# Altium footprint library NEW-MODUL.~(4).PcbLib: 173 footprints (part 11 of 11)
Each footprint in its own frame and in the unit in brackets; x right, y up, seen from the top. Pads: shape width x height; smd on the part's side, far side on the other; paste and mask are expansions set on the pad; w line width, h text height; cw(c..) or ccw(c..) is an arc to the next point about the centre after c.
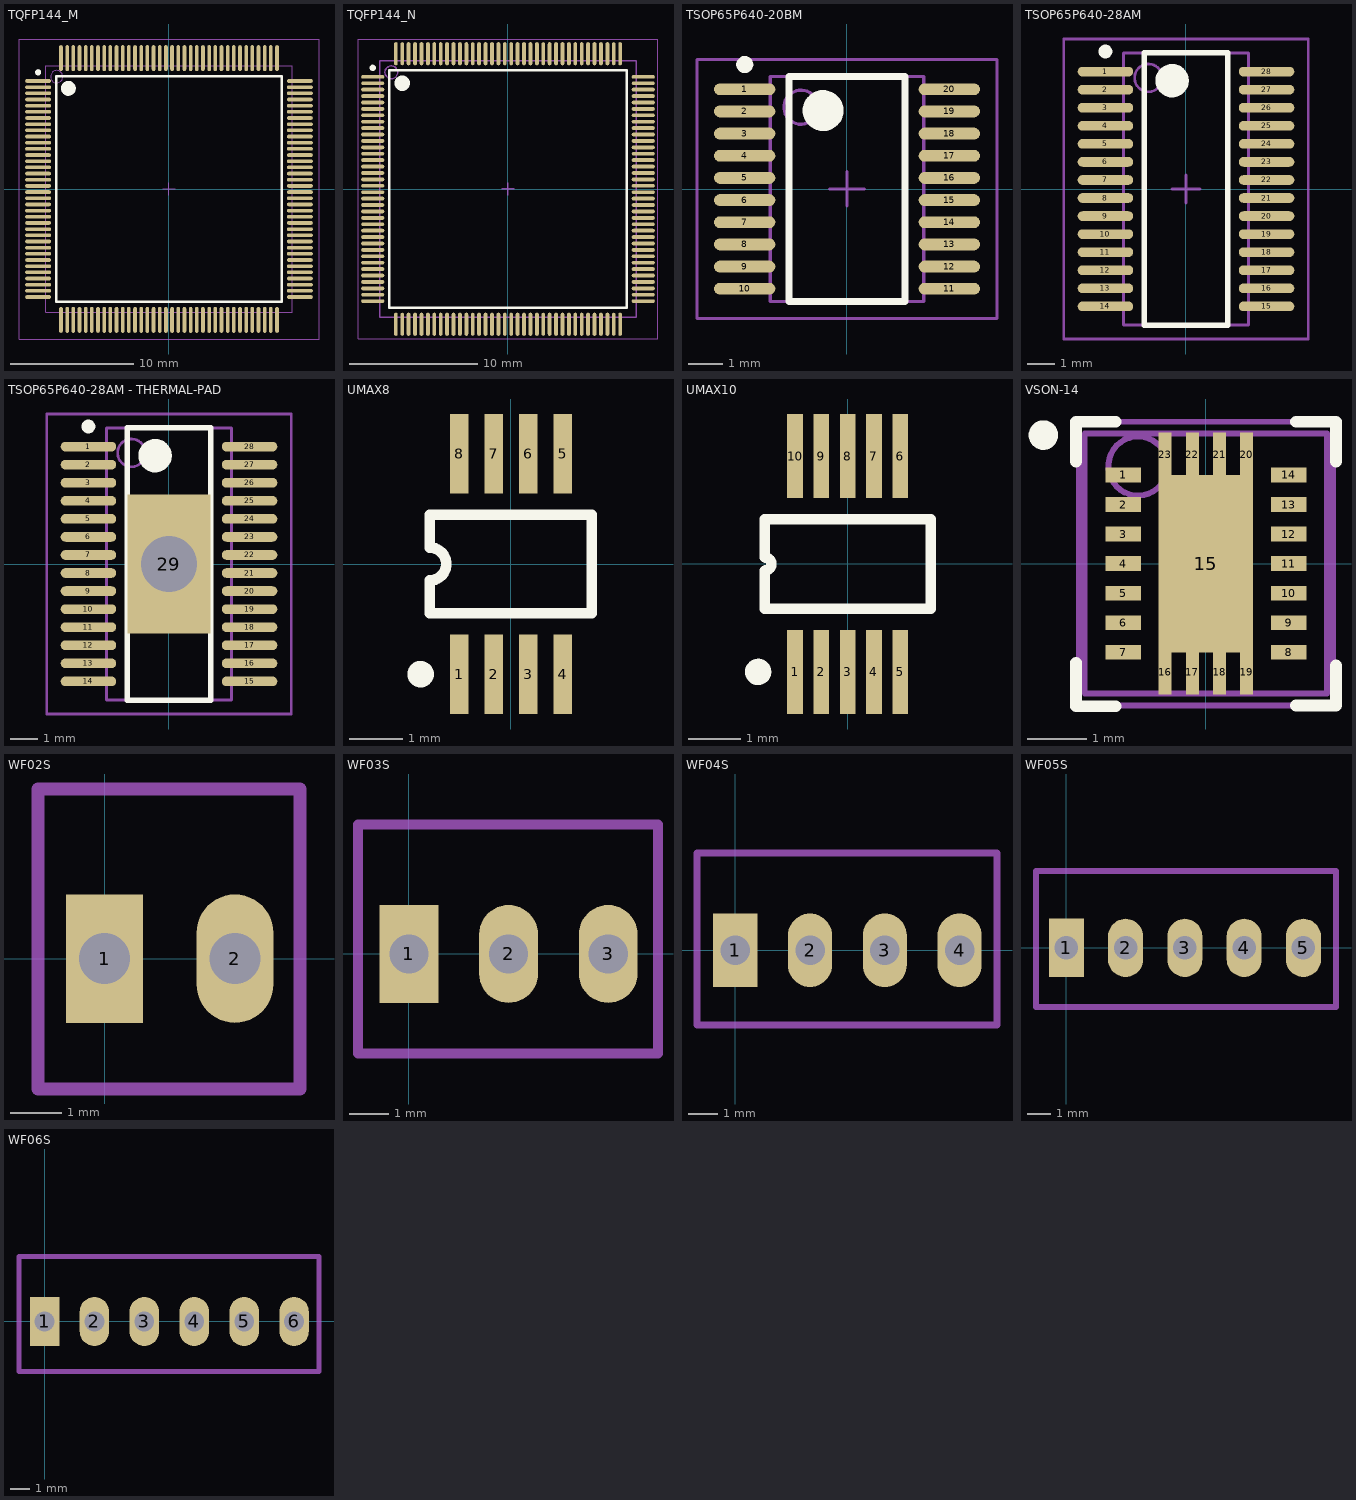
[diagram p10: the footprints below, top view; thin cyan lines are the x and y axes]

## TQFP144_M [mm] "Thin QFP, 144-Leads, Body 20x20mm, Pitch 0.5mm, IPC Low Density"
height 1.6
pads (144):
  oval 2.1x0.3 smd: 1(-10.6,8.75) 2(-10.6,8.25) 3(-10.6,7.75) 4(-10.6,7.25) 5(-10.6,6.75) 6(-10.6,6.25) 7(-10.6,5.75) 8(-10.6,5.25) 9(-10.6,4.75) 10(-10.6,4.25) 11(-10.6,3.75) 12(-10.6,3.25) 13(-10.6,2.75) 14(-10.6,2.25) 15(-10.6,1.75) 16(-10.6,1.25) 17(-10.6,0.75) 18(-10.6,0.25) 19(-10.6,-0.25) 20(-10.6,-0.75) 21(-10.6,-1.25) 22(-10.6,-1.75) 23(-10.6,-2.25) 24(-10.6,-2.75) 25(-10.6,-3.25) 26(-10.6,-3.75) 27(-10.6,-4.25) 28(-10.6,-4.75) 29(-10.6,-5.25) 30(-10.6,-5.75) 31(-10.6,-6.25) 32(-10.6,-6.75) 33(-10.6,-7.25) 34(-10.6,-7.75) 35(-10.6,-8.25) 36(-10.6,-8.75) 73(10.6,-8.75) 74(10.6,-8.25) 75(10.6,-7.75) 76(10.6,-7.25) 77(10.6,-6.75) 78(10.6,-6.25) 79(10.6,-5.75) 80(10.6,-5.25) 81(10.6,-4.75) 82(10.6,-4.25) 83(10.6,-3.75) 84(10.6,-3.25) 85(10.6,-2.75) 86(10.6,-2.25) 87(10.6,-1.75) 88(10.6,-1.25) 89(10.6,-0.75) 90(10.6,-0.25) 91(10.6,0.25) 92(10.6,0.75) 93(10.6,1.25) 94(10.6,1.75) 95(10.6,2.25) 96(10.6,2.75) 97(10.6,3.25) 98(10.6,3.75) 99(10.6,4.25) 100(10.6,4.75) 101(10.6,5.25) 102(10.6,5.75) 103(10.6,6.25) 104(10.6,6.75) 105(10.6,7.25) 106(10.6,7.75) 107(10.6,8.25) 108(10.6,8.75)
  oval 0.3x2.1 smd: 37(-8.75,-10.6) 38(-8.25,-10.6) 39(-7.75,-10.6) 40(-7.25,-10.6) 41(-6.75,-10.6) 42(-6.25,-10.6) 43(-5.75,-10.6) 44(-5.25,-10.6) 45(-4.75,-10.6) 46(-4.25,-10.6) 47(-3.75,-10.6) 48(-3.25,-10.6) 49(-2.75,-10.6) 50(-2.25,-10.6) 51(-1.75,-10.6) 52(-1.25,-10.6) 53(-0.75,-10.6) 54(-0.25,-10.6) 55(0.25,-10.6) 56(0.75,-10.6) 57(1.25,-10.6) 58(1.75,-10.6) 59(2.25,-10.6) 60(2.75,-10.6) 61(3.25,-10.6) 62(3.75,-10.6) 63(4.25,-10.6) 64(4.75,-10.6) 65(5.25,-10.6) 66(5.75,-10.6) 67(6.25,-10.6) 68(6.75,-10.6) 69(7.25,-10.6) 70(7.75,-10.6) 71(8.25,-10.6) 72(8.75,-10.6) 109(8.75,10.6) 110(8.25,10.6) 111(7.75,10.6) 112(7.25,10.6) 113(6.75,10.6) 114(6.25,10.6) 115(5.75,10.6) 116(5.25,10.6) 117(4.75,10.6) 118(4.25,10.6) 119(3.75,10.6) 120(3.25,10.6) 121(2.75,10.6) 122(2.25,10.6) 123(1.75,10.6) 124(1.25,10.6) 125(0.75,10.6) 126(0.25,10.6) 127(-0.25,10.6) 128(-0.75,10.6) 129(-1.25,10.6) 130(-1.75,10.6) 131(-2.25,10.6) 132(-2.75,10.6) 133(-3.25,10.6) 134(-3.75,10.6) 135(-4.25,10.6) 136(-4.75,10.6) 137(-5.25,10.6) 138(-5.75,10.6) 139(-6.25,10.6) 140(-6.75,10.6) 141(-7.25,10.6) 142(-7.75,10.6) 143(-8.25,10.6) 144(-8.75,10.6)
Top Overlay:
  circle w0.6: c-8.15,8.15 r0.3
  circle w0.25: c-10.6,9.45 r0.125
  lines w0.2: -9.15,-9.15 9.15,-9.15 9.15,9.15 -9.15,9.15 -9.15,-9.15
Mechanical 13:
  circle w0.1: c-9.1,9.1 r0.5
  lines w0.1: -10,-10 10,-10 10,10 -10,10 -10,-10
Mechanical 15:
  lines w0.05: -12.15,-12.15 12.15,-12.15 12.15,12.15 -12.15,12.15 -12.15,-12.15
  lines w0.1: -0.5,0 0.5,0 ; 0,-0.5 0,0.5
3D body: height 1.6, standoff 0, extent -10,-10 10,10

## TQFP144_N [mm] "Thin QFP, 144-Leads, Body 20x20mm, Pitch 0.5mm, IPC Medium Density"
height 1.6
pads (144):
  oval 1.8x0.3 smd: 1(-10.55,8.75) 2(-10.55,8.25) 3(-10.55,7.75) 4(-10.55,7.25) 5(-10.55,6.75) 6(-10.55,6.25) 7(-10.55,5.75) 8(-10.55,5.25) 9(-10.55,4.75) 10(-10.55,4.25) 11(-10.55,3.75) 12(-10.55,3.25) 13(-10.55,2.75) 14(-10.55,2.25) 15(-10.55,1.75) 16(-10.55,1.25) 17(-10.55,0.75) 18(-10.55,0.25) 19(-10.55,-0.25) 20(-10.55,-0.75) 21(-10.55,-1.25) 22(-10.55,-1.75) 23(-10.55,-2.25) 24(-10.55,-2.75) 25(-10.55,-3.25) 26(-10.55,-3.75) 27(-10.55,-4.25) 28(-10.55,-4.75) 29(-10.55,-5.25) 30(-10.55,-5.75) 31(-10.55,-6.25) 32(-10.55,-6.75) 33(-10.55,-7.25) 34(-10.55,-7.75) 35(-10.55,-8.25) 36(-10.55,-8.75) 73(10.55,-8.75) 74(10.55,-8.25) 75(10.55,-7.75) 76(10.55,-7.25) 77(10.55,-6.75) 78(10.55,-6.25) 79(10.55,-5.75) 80(10.55,-5.25) 81(10.55,-4.75) 82(10.55,-4.25) 83(10.55,-3.75) 84(10.55,-3.25) 85(10.55,-2.75) 86(10.55,-2.25) 87(10.55,-1.75) 88(10.55,-1.25) 89(10.55,-0.75) 90(10.55,-0.25) 91(10.55,0.25) 92(10.55,0.75) 93(10.55,1.25) 94(10.55,1.75) 95(10.55,2.25) 96(10.55,2.75) 97(10.55,3.25) 98(10.55,3.75) 99(10.55,4.25) 100(10.55,4.75) 101(10.55,5.25) 102(10.55,5.75) 103(10.55,6.25) 104(10.55,6.75) 105(10.55,7.25) 106(10.55,7.75) 107(10.55,8.25) 108(10.55,8.75)
  oval 0.3x1.8 smd: 37(-8.75,-10.55) 38(-8.25,-10.55) 39(-7.75,-10.55) 40(-7.25,-10.55) 41(-6.75,-10.55) 42(-6.25,-10.55) 43(-5.75,-10.55) 44(-5.25,-10.55) 45(-4.75,-10.55) 46(-4.25,-10.55) 47(-3.75,-10.55) 48(-3.25,-10.55) 49(-2.75,-10.55) 50(-2.25,-10.55) 51(-1.75,-10.55) 52(-1.25,-10.55) 53(-0.75,-10.55) 54(-0.25,-10.55) 55(0.25,-10.55) 56(0.75,-10.55) 57(1.25,-10.55) 58(1.75,-10.55) 59(2.25,-10.55) 60(2.75,-10.55) 61(3.25,-10.55) 62(3.75,-10.55) 63(4.25,-10.55) 64(4.75,-10.55) 65(5.25,-10.55) 66(5.75,-10.55) 67(6.25,-10.55) 68(6.75,-10.55) 69(7.25,-10.55) 70(7.75,-10.55) 71(8.25,-10.55) 72(8.75,-10.55) 109(8.75,10.55) 110(8.25,10.55) 111(7.75,10.55) 112(7.25,10.55) 113(6.75,10.55) 114(6.25,10.55) 115(5.75,10.55) 116(5.25,10.55) 117(4.75,10.55) 118(4.25,10.55) 119(3.75,10.55) 120(3.25,10.55) 121(2.75,10.55) 122(2.25,10.55) 123(1.75,10.55) 124(1.25,10.55) 125(0.75,10.55) 126(0.25,10.55) 127(-0.25,10.55) 128(-0.75,10.55) 129(-1.25,10.55) 130(-1.75,10.55) 131(-2.25,10.55) 132(-2.75,10.55) 133(-3.25,10.55) 134(-3.75,10.55) 135(-4.25,10.55) 136(-4.75,10.55) 137(-5.25,10.55) 138(-5.75,10.55) 139(-6.25,10.55) 140(-6.75,10.55) 141(-7.25,10.55) 142(-7.75,10.55) 143(-8.25,10.55) 144(-8.75,10.55)
Top Overlay:
  circle w0.25: c-10.55,9.45 r0.125
  circle w0.6: c-8.25,8.25 r0.3
  lines w0.2: -9.25,-9.25 -9.25,9.25 9.25,9.25 9.25,-9.25 -9.25,-9.25
Mechanical 13:
  circle w0.1: c-9.1,9.1 r0.5
  lines w0.1: -10,-10 -10,10 10,10 10,-10 -10,-10
Mechanical 15:
  lines w0.05: -11.7,-11.7 -11.7,11.7 11.7,11.7 11.7,-11.7 -11.7,-11.7
  lines w0.1: -0.5,0 0.5,0 ; 0,-0.5 0,0.5
3D body: height 1.6, standoff 0, extent -10,-10 10,10

## TSOP65P640-20BM [mm] "TSOP, 20-Leads, Body 6.5x4.4mm, Pitch 0.65mm, IPC Low Density"
height 1.2
pads (20):
  oval 1.8x0.35 smd: 1(-3,2.925) 2(-3,2.275) 3(-3,1.625) 4(-3,0.975) 5(-3,0.325) 6(-3,-0.325) 7(-3,-0.975) 8(-3,-1.625) 9(-3,-2.275) 10(-3,-2.925) 11(3,-2.925) 12(3,-2.275) 13(3,-1.625) 14(3,-0.975) 15(3,-0.325) 16(3,0.325) 17(3,0.975) 18(3,1.625) 19(3,2.275) 20(3,2.925)
Top Overlay:
  circle w0.25: c-3,3.65 r0.125
  circle w0.6: c-0.7,2.3 r0.3
  lines w0.2: -1.7,-3.3 -1.7,3.3 1.7,3.3 1.7,-3.3 -1.7,-3.3
Mechanical 13:
  circle w0.1: c-1.35,2.4 r0.5
  lines w0.1: -2.25,-3.3 -2.25,3.3 2.25,3.3 2.25,-3.3 -2.25,-3.3
Mechanical 15:
  lines w0.1: -0.5,0 0.5,0 ; 0,-0.5 0,0.5 ; -4.4,-3.8 -4.4,3.8 4.4,3.8 4.4,-3.8 -4.4,-3.8
3D body "User Library-TSSOP-20 6_6x4_4.STEP": height 1.12, standoff 0.02, extent -3.2,-3.3 3.2,3.3

## TSOP65P640-28AM [mm] "TSOP, 28-Leads, Body 9.7x4.4mm, Pitch 0.65mm, IPC Low Density"
height 1.1
pads (28):
  oval 2x0.35 smd: 1(-2.9,4.225) 2(-2.9,3.575) 3(-2.9,2.925) 4(-2.9,2.275) 5(-2.9,1.625) 6(-2.9,0.975) 7(-2.9,0.325) 8(-2.9,-0.325) 9(-2.9,-0.975) 10(-2.9,-1.625) 11(-2.9,-2.275) 12(-2.9,-2.925) 13(-2.9,-3.575) 14(-2.9,-4.225) 15(2.9,-4.225) 16(2.9,-3.575) 17(2.9,-2.925) 18(2.9,-2.275) 19(2.9,-1.625) 20(2.9,-0.975) 21(2.9,-0.325) 22(2.9,0.325) 23(2.9,0.975) 24(2.9,1.625) 25(2.9,2.275) 26(2.9,2.925) 27(2.9,3.575) 28(2.9,4.225)
Top Overlay:
  circle w0.25: c-2.9,4.95 r0.125
  circle w0.6: c-0.5,3.9 r0.3
  lines w0.2: -1.5,-4.9 -1.5,4.9 1.5,4.9 1.5,-4.9 -1.5,-4.9
Mechanical 13:
  circle w0.1: c-1.35,4 r0.5
  lines w0.1: -2.25,-4.9 -2.25,4.9 2.25,4.9 2.25,-4.9 -2.25,-4.9
Mechanical 15:
  lines w0.1: -0.5,0 0.5,0 ; 0,-0.5 0,0.5 ; -4.4,-5.4 -4.4,5.4 4.4,5.4 4.4,-5.4 -4.4,-5.4
3D body "SW3dPS-TSSOP-28_P065.STEP": height 1.09, standoff 0.01, extent -3.206,-4.85 3.207,4.85

## TSOP65P640-28AM - THERMAL-PAD [mm] "TSOP, 28-Leads, Body 9.7x4.4mm, Pitch 0.65mm, IPC Low Density"
height 1.1
pads (29):
  oval 2x0.35 smd: 1(-2.9,4.225) 2(-2.9,3.575) 3(-2.9,2.925) 4(-2.9,2.275) 5(-2.9,1.625) 6(-2.9,0.975) 7(-2.9,0.325) 8(-2.9,-0.325) 9(-2.9,-0.975) 10(-2.9,-1.625) 11(-2.9,-2.275) 12(-2.9,-2.925) 13(-2.9,-3.575) 14(-2.9,-4.225) 15(2.9,-4.225) 16(2.9,-3.575) 17(2.9,-2.925) 18(2.9,-2.275) 19(2.9,-1.625) 20(2.9,-0.975) 21(2.9,-0.325) 22(2.9,0.325) 23(2.9,0.975) 24(2.9,1.625) 25(2.9,2.275) 26(2.9,2.925) 27(2.9,3.575) 28(2.9,4.225)
  rect 3x5 / inner round 2 / far side rect 3x3 hole 2: 29(0,0)
Top Overlay:
  circle w0.25: c-2.9,4.95 r0.125
  circle w0.6: c-0.5,3.9 r0.3
  lines w0.2: -1.5,-4.9 -1.5,4.9 1.5,4.9 1.5,-4.9 -1.5,-4.9
Mechanical 13:
  circle w0.1: c-1.35,4 r0.5
  lines w0.1: -2.25,-4.9 -2.25,4.9 2.25,4.9 2.25,-4.9 -2.25,-4.9
Mechanical 15:
  lines w0.1: -0.5,0 0.5,0 ; 0,-0.5 0,0.5 ; -4.4,-5.4 -4.4,5.4 4.4,5.4 4.4,-5.4 -4.4,-5.4
3D body "SW3dPS-TSSOP-28_P065.STEP": height 1.09, standoff 0.01, extent -3.206,-4.85 3.207,4.85

## UMAX8 [mm] "Shrink Small Outline; 8 Leads; Body Width 3 mm; Pitch 0.65 mm"
height 1.1
pads (8):
  rect 0.35x1.5 smd: 1(-0.975,-2.075) 2(-0.325,-2.075) 3(0.325,-2.075) 4(0.975,-2.075) 5(0.975,2.075) 6(0.325,2.075) 7(-0.325,2.075) 8(-0.975,2.075)
Top Overlay:
  circle w0.25: c-1.7,-2.075 r0.125
  lines w0.2: -1.525,-0.925 -1.525,-0.308 ccw(c-1.525,0) -1.525,0.308 -1.525,0.925 1.525,0.925 1.525,-0.925 -1.525,-0.925
3D body "SW3dPS-uMAX8.STEP": height 0.95, standoff 0, extent -1.5,-2.5 1.5,2.5

## UMAX10 [mm] "Shrink Small Outline; 10 Leads; Body Width 3 mm; Pitch 0.5 mm"
height 1.1
pads (10):
  rect 0.3x1.6 smd: 1(-1,-2.05) 2(-0.5,-2.05) 3(0,-2.05) 4(0.5,-2.05) 5(1,-2.05) 6(1,2.05) 7(0.5,2.05) 8(0,2.05) 9(-0.5,2.05) 10(-1,2.05)
Top Overlay:
  circle w0.25: c-1.7,-2.05 r0.125
  lines w0.2: -1.575,-0.85 -1.575,-0.125 ccw(c-1.575,0) -1.575,0.125 -1.575,0.85 1.575,0.85 1.575,-0.85 -1.575,-0.85
3D body "SW3dPS-uMAX10.STEP": height 0.95, standoff 0, extent -1.5,-2.5 1.5,2.5

## VSON-14 [mm] "PQFN, 24-Leads, Body 5x4mm, Pitch 0.5mm, NSC Recommended"
height 0.8
pads (23):
  rect 0.6x0.25 smd paste-0.2 mask+0.051: 1(-1.4,1.5) 2(-1.4,1) 3(-1.4,0.5) 4(-1.4,0) 5(-1.4,-0.5) 6(-1.4,-1) 7(-1.4,-1.5) 8(1.4,-1.5) 9(1.4,-1) 10(1.4,-0.5) 11(1.4,0) 12(1.4,0.5) 13(1.4,1) 14(1.4,1.5)
  rect 1.6x3 smd paste-1.2 mask+0.051: 15(0,0)
  rect 0.22x0.75 smd paste-0.2 mask+0.051: 16(-0.69,-1.84) 17(-0.23,-1.84) 18(0.23,-1.84) 19(0.69,-1.84) 20(0.69,1.84) 21(0.23,1.84) 22(-0.23,1.84) 23(-0.69,1.84)
Top Overlay:
  circle w0.25: c-2.75,2.175 r0.125
  lines w0.2: -2.2,-1.676 -2.2,-2.413 -1.525,-2.413 ; -2.2,1.725 -2.2,2.4 -1.525,2.4 ; 1.525,-2.4 2.2,-2.4 2.2,-1.725 ; 1.525,2.4 2.2,2.4 2.2,1.725
Mechanical 13:
  circle w0.1: c-1.15,1.65 r0.5
  lines w0.1: -2.05,-2.2 -2.05,2.2 2.05,2.2 2.05,-2.2 -2.05,-2.2
Mechanical 15:
  lines w0.1: -0.5,0 0.5,0 ; 0,-0.5 0,0.5 ; -2.15,-2.4 -2.15,2.4 2.15,2.4 2.15,-2.4 -2.15,-2.4
3D body "User Library-VSON-14-1.step": height 1, standoff -0.05, extent -1.607,-2.101 1.603,2.109

## WF02S [mm]
pads (2):
  rect 1.5x2.5 hole 1: 1(0,0)
  oval 1.5x2.5 hole 1: 2(2.54,0)
Mechanical 15:
  lines w0.254: -1.3,-2.54 3.81,-2.54 3.81,3.302 -1.3,3.302 -1.3,-2.54
3D body "User Library-CI31_2.step": height 11.51, standoff -3.29, extent -1.27,-2.521 3.81,3.279

## WF03S [mm]
pads (3):
  rect 1.5x2.5 hole 1: 1(0,0)
  oval 1.5x2.5 hole 1: 2(2.54,0) 3(5.08,0)
Mechanical 15:
  lines w0.254: -1.3,-2.54 -1.3,3.302 6.35,3.302 6.35,-2.54 -1.3,-2.54
3D body "User Library-CI31_3.step": height 11.51, standoff -3.29, extent -1.27,-2.521 6.35,3.279

## WF04S [mm]
pads (4):
  rect 1.5x2.5 hole 1: 1(0,0)
  oval 1.5x2.5 hole 1: 2(2.54,0) 3(5.08,0) 4(7.62,0)
Mechanical 15:
  lines w0.254: -1.3,-2.54 -1.3,3.302 8.89,3.302 8.89,-2.54 -1.3,-2.54
3D body "User Library-CI31_4.step": height 11.51, standoff -3.29, extent -1.27,-2.54 8.89,3.26

## WF05S [mm]
pads (5):
  rect 1.5x2.5 hole 1: 1(0,0)
  oval 1.5x2.5 hole 1: 2(2.54,0) 3(5.08,0) 4(7.62,0) 5(10.16,0)
Mechanical 15:
  lines w0.254: -1.3,-2.54 -1.3,3.302 11.557,3.302 11.557,-2.54 -1.3,-2.54
3D body "User Library-CI31_5_new.step": height 11.51, standoff -3.29, extent -1.27,-2.521 11.43,3.279

## WF06S [mm]
pads (6):
  rect 1.5x2.5 hole 1: 1(0,0)
  oval 1.5x2.5 hole 1: 2(2.54,0) 3(5.08,0) 4(7.62,0) 5(10.16,0) 6(12.7,0)
Mechanical 15:
  lines w0.254: -1.3,-2.54 13.97,-2.54 13.97,3.302 -1.3,3.302 -1.3,-2.54
3D body "User Library-CI31_6.step": height 11.51, standoff -3.29, extent -1.27,-2.521 13.97,3.279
